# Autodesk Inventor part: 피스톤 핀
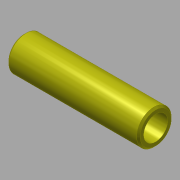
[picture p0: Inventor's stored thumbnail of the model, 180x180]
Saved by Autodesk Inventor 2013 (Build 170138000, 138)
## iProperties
Created: 2017-05
Part Number: 피스톤 핀
Material: 알루미늄 6061
Document SubType Name: Modeling
Designer: mduedu
Density: 2.71 g/cm^3
Mass: 4.10432 g
Surface Area: 20.9053 cm^2
Volume: 1.51451 cm^3
Author: mduedu
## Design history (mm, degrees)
sketch "스케치1"
  geometry: C1 r 5 at (0, 0); C2 r 3.5 at (0, 0); 1 further point
  constraints: 2 centre point, 2 coincident
  dimensions: "d0" = 10 diameter of C1; "d1" = 7 diameter of C2
extrude "돌출1" new body sketch "스케치1" stored distance "d2" = 38; taper "d3" = 0 deg
chamfer "모따기1" distance "d4" = 0.5; stored, may be unused: second distance "d5" = 2, angle "d6" = 45 deg
node "솔리드1"
